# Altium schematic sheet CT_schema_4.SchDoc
size 143 x 123 mm
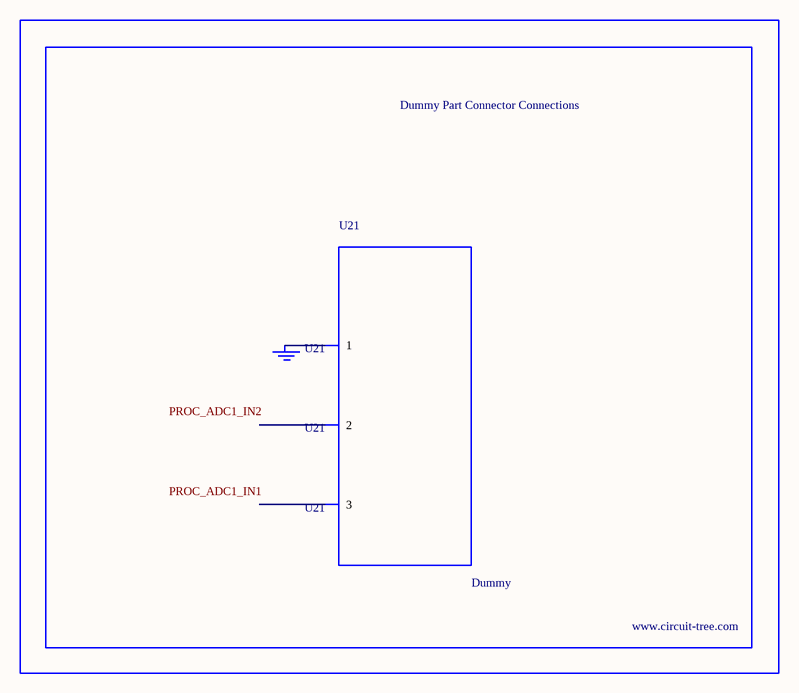
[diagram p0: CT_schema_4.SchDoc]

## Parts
BORDER3  (no value)
GND_INSTANCE_3_0  (no value)
U21  Dummy  [DUMMY_PACKAGE_166]

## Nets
NetGND_INSTANCE_3_0_0: GND_INSTANCE_3_0.0(GND) U21.1

Not connected (* = marked no-connect by the designer): U21 2 3

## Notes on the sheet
- Labels drawn without touching a wire or pin: PROC_ADC1_IN1, PROC_ADC1_IN2

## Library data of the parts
BORDER3 = BORDER_PAGE3
GND_INSTANCE_3_0 = GND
